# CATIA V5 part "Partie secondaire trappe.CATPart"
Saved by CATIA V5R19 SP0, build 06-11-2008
Part number: Partie secondaire tarppe
Bounding box of the stored display mesh (mm): x -80.186 to 40.336, y -7.5 to 7.5, z 0 to 28.822
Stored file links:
  G:\EU_thinkMotion\CFAO_2010\St2M_groupe2\St2M_groupe2\csayed\csayed\csayed\Partie secondaire trappe.CATPart
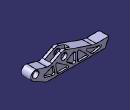
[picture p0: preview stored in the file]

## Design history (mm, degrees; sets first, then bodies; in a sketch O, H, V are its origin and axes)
Body1 (main body)
  Sketch1 on zx-plane, origin (0, 0, 0), H (-1, 0, 0), V (0, 0, 1)
    line L1 (-15.4437, 0) -> (74.5563, 0)
    point P1 (-15.4437, 0)
    line L2 (74.5563, 0) -> (80.1855, 13.0112)
    line L3 (80.1855, 13.0112) -> (60.5124, 13.0112)
    line L4 (-19.7889, 1.8889) -> (-36.9203, 11.6131)
    connectcurve C1
    line L5 (54.1991, 14.069) -> (14.0885, 28.1185)
    connectcurve C2
    arc A1 centre (-33.4648, 17.7008) radius 7 from (-31.507, 24.4214) to (-36.9203, 11.6131) ccw
    line L6 (-31.507, 24.4214) -> (-15.7522, 19.832)
    line L7 (6.2872, 27.6138) -> (-7.6263, 20.7324)
    connectcurve C3
    connectcurve C4
    coincidence: P1 H
    horizontal: L1 H, L3 H
    tangency: A1 L4, L6 A1
  Pad1: profile Sketch1, direction (0, 1, 0), length 7.5, mirrored extent
  Sketch2 on end face of Pad1, origin (0, 7.5, 0), H (-1, 0, 0), V (0, 0, 1)
    circle A1 centre (-32.7266, 18.253) radius 5
    circle A2 centre (10.9909, 20.7518) radius 5
  Pocket1: profile Sketch2, direction (0, -1, 0), through (limit type 3)
  Sketch3 on end face of Pad1, origin (0, 7.5, 0), H (-1, 0, 0), V (0, 0, 1)
    line L1 (-18.8596, 11.4483) -> (-8.2183, 16.3261)
    line L2 (-18.8596, 7.7259) -> (-6.1586, 3.6183)
    line L3 (-4.7855, 14.1439) -> (-3.3372, 5.6776)
    connectcurve C1
    connectcurve C2
    connectcurve C3
    line L4 (-1.9703, 15.4788) -> (0.0477, 3.6821)
    point P8 (0.0477, 3.6821)
    line L5 (2.7664, 2.3347) -> (16.7207, 2.3347)
    connectcurve C4
    line L6 (0, 17.6097) -> (16.7207, 5.6776)
    point P11 (0, 17.6097)
    connectcurve C5
    connectcurve C6
    line L7 (15.7311, 10.0694) -> (25.2645, 3.2662)
    line L8 (28.6833, 16.3261) -> (28.6833, 5.6776)
    line L9 (17.094, 14.2078) -> (24.4174, 18.7298)
    connectcurve C7
    connectcurve C8
    connectcurve C9
    line L10 (31.6833, 16.3261) -> (31.6833, 4.6452)
    line L11 (34.541, 2.3347) -> (47.5632, 2.3347)
    point P21 (34.541, 2.3347)
    line L12 (34.541, 17.6097) -> (47.9062, 4.2959)
    connectcurve C10
    connectcurve C11
    connectcurve C12
    line L13 (45.4714, 10.9559) -> (52.2978, 4.1557)
    line L14 (57.1748, 2.3347) -> (67.118, 4.6452)
    point P27 (57.1748, 2.3347)
    connectcurve C13
    spline S1 through (47.12, 13.5626) (59.5898, 9.0487) (67.4305, 7.7896)
    connectcurve C14
    connectcurve C15
    distance L3 L4 = 3
    distance L6 L7 = 3
    distance L10 L8 = 3
    distance L13 L12 = 3
    horizontal: L5 H, L11 H
    coincidence: P11 V, L9 P8, P21 L5, P27 L5
    vertical: L8 V, L10 V
  Pocket2: profile Sketch3, direction (0, -1, 0), length 3
  Mirror1: of Pocket2, about zx-plane
  Sketch4 on xy-plane, origin (0, 0, 0), H (1, 0, 0), V (0, 1, 0)
    line L1 (-23, -3.5) -> (8, -3.5)
    line L2 (8, -3.5) -> (8, 3.5)
    line L3 (8, 3.5) -> (-23, 3.5)
    line L4 (-23, 3.5) -> (-23, -3.5)
    horizontal: L1 H, L3 H
    vertical: L2 V, L4 V
  Pocket3: profile Sketch4, direction (0, 0, 1), length 31.5, opposite side length -9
